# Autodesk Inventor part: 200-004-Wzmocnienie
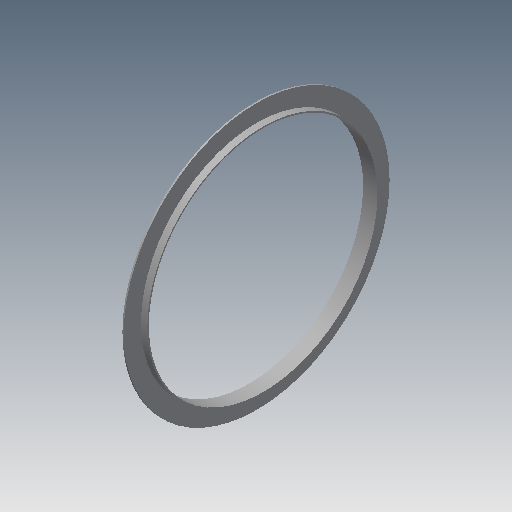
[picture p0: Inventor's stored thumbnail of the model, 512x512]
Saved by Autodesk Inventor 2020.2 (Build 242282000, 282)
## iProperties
Created: 2014-03
Part Number: 200-004-Wzmocnienie
Material: Stal
Document SubType Name: Modeling
Designer: F.Stasiak
Density: 7.85 g/cm^3
Appearance: Stal
Catalog Web Link: www.expertbooks.pl
Manager: www.cadconsulting.pl
Company: Fabian Stasiak CAD Consulting
Author: F.Stasiak
Subject: Zbiór ćwiczeń. Autodesk Inventor 2020. Kurs Professional
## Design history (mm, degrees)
sketch "Szkic1"
  geometry: L1 (0, 810)-(100, 810); L2 (100, 810)-(100, 800); L3 (100, 800)-(0, 800); L4 (0, 800)-(0, 810); L5 (45, 930)-(55, 930); L6 (55, 930)-(55, 810); L7 (55, 810)-(45, 810); L8 (45, 810)-(45, 930); L9 (0, 0)-(100, 0); 1 further point
  constraints: 18 end point, 5 parallel, 3 perpendicular, 2 horizontal, 2 midpoint, 1 vertical alignment
  dimensions: "d0" = 100 distance of L2.end L3.end; "d1" = 10 distance of L1.end L2.end; "d2" = 800 distance from line of L9.start L3; "d3" = 10 distance of L6.end L7.end; "d4" = 120 distance of L5.end L6.end
revolve "Obrót1" sketch "Szkic1" stored, may be unused: angle "d5" = 90 deg
node "Bryła1"
